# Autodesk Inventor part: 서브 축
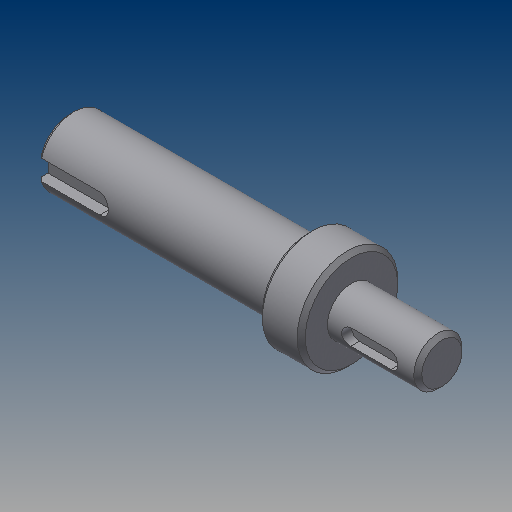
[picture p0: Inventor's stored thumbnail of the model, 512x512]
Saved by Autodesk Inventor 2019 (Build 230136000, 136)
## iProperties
Created: 2014-10
Part Number: 서브 축
Document SubType Name: Modeling
Designer: KYOUNG IL JANG
Density: 1 g/cm^3
Mass: 19.9624 g
Surface Area: 57.7178 cm^2
Volume: 19.9624 cm^3
Material: 강철, 연강
Appearance: 금속-강(스테인리스, 브러시됨)
Author: SeoGD™ [www.esajin.kr]
Revision Number: 1
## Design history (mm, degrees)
sketch "스케치1"
  geometry: L1 (-16.331, 0)-(-108.831, 0); L2 (-16.331, 0)-(-16.331, -6); L3 (-16.331, -6)-(-38.831, -6); L4 (-38.831, -12.5)-(-46.5, -12.5); L5 (-46.5, -8.5)-(-108.831, -8.5); L6 (-108.831, -8.5)-(-108.831, 0); L7 (-46.5, -8.5)-(-46.5, -12.5); L8 (-38.831, -6)-(-38.831, -12.5); L9 (-46.5, 12.249)-(-46.5, -12.249) reference; L10 (-38.831, -17)-(-38.831, 17) reference; 2 further points
  constraints: 17 end point, 4 perpendicular, 2 collinear, 2 parallel, 1 horizontal, 1 midpoint, 1 point on line
  dimensions: "d1" = 12 diameter of L3 L1; "d2" = 25 diameter of L4 L1; "d3" = 17 diameter of L5 L1; "d18" = 22.5 distance of L2.end L3.end; "d20" = 70 distance between parallel lines of L6 L8; "d21" = 7.66872 distance of L4.start L4.end (derived)
revolve "회전1" sketch "스케치1" stored, may be unused: angle "d5" = 90 deg
chamfer "모따기1" distance "d6" = 1; stored, may be unused: second distance "d7" = 2, angle "d8" = 45 deg
node "작업 평면1"
sketch "스케치2"
  geometry: L1 (11.25, 5)-(11.25, -5) reference; L2 (-5.75, -2)-(4.25, -2); L3 (4.25, 2)-(-5.75, 2); A1 r 2 centre (4.25, 0) between (4.25, -2) and (4.25, 2); A2 r 2 centre (-5.75, 0) between (-5.75, 2) and (-5.75, -2); 2 further points
  constraints: 4 end point, 4 point on circle, 4 tangent, 2 centre point, 1 horizontal alignment, 1 midpoint, 1 parallel, 1 perpendicular
  dimensions: "d9" = 4 distance between parallel lines of L2 L3; "d10" = 14 dimension on A1 A2; "d11" = 5 distance edge to line of A1 L1
extrude "돌출1" cut sketch "스케치2" distance "d12" = 2.5; taper "d13" = 0 deg
node "작업 평면2"
sketch "스케치3"
  geometry: L1 (-31.166, -7.5)-(-31.166, 7.5) reference; L2 (-31.166, 2.5)-(-15.666, 2.5); L3 (-15.666, -2.5)-(-31.166, -2.5); A1 r 2.5 centre (-15.666, 0) between (-15.666, -2.5) and (-15.666, 2.5); 2 further points
  constraints: 4 end point, 2 perpendicular, 2 point on circle, 2 point on line, 2 tangent, 1 centre point, 1 horizontal alignment, 1 midpoint
  dimensions: "d14" = 5 distance between parallel lines of L3 L2; "d15" = 18 dimension on A1 L1
extrude "돌출2" cut sketch "스케치3" distance "d16" = 3; taper "d17" = 0 deg
sketch "스케치4"
  geometry: C1 r 12.5 at (0, 0) reference; 1 further point
extrude "돌출3" join sketch "스케치4" distance "d22" = 3; taper "d23" = 0 deg
chamfer "모따기2" distance "d24" = 1; stored, may be unused: second distance "d25" = 2, angle "d26" = 45 deg
node "솔리드1"
node "참조4"
node "참조5"
